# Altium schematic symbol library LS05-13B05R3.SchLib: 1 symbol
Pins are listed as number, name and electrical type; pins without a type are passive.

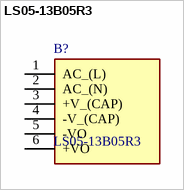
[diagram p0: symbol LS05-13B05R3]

## LS05-13B05R3
designator B?
AC DC CONVERTER,5W,5VDC; Manufacturer_Name: Morunsun; Geometry.Height: 15.73mm
footprint LS0513B05R3
pins: 1 AC_(L), 2 AC_(N), 3 +V_(CAP), 4 -V_(CAP), 5 -VO, 6 +VO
